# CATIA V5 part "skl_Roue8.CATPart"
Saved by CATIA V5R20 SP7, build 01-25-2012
Part number: skl_Roue8
Publications: "Axe_Roue8", "Plan.1", "Point.2"
Bounding box of the stored display mesh (mm): x 0 to 20, y 0 to 0, z 68 to 68
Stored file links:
  J:\ACHTUNG2\skl_Roue8.CATPart
  J:\cmilovidofIAO\skl_IAO.CATProduct
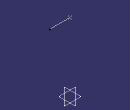
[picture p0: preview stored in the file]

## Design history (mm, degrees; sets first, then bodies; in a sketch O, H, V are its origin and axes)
Set1
  Plane1: linked copy from another document
  Point1 "Point.2": linked copy from another document
Body1 (main body)
  Line1 "Axe_Roue8": type Normal, RefPoint Point1, RefSkin Plane1, Start 0, End 20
